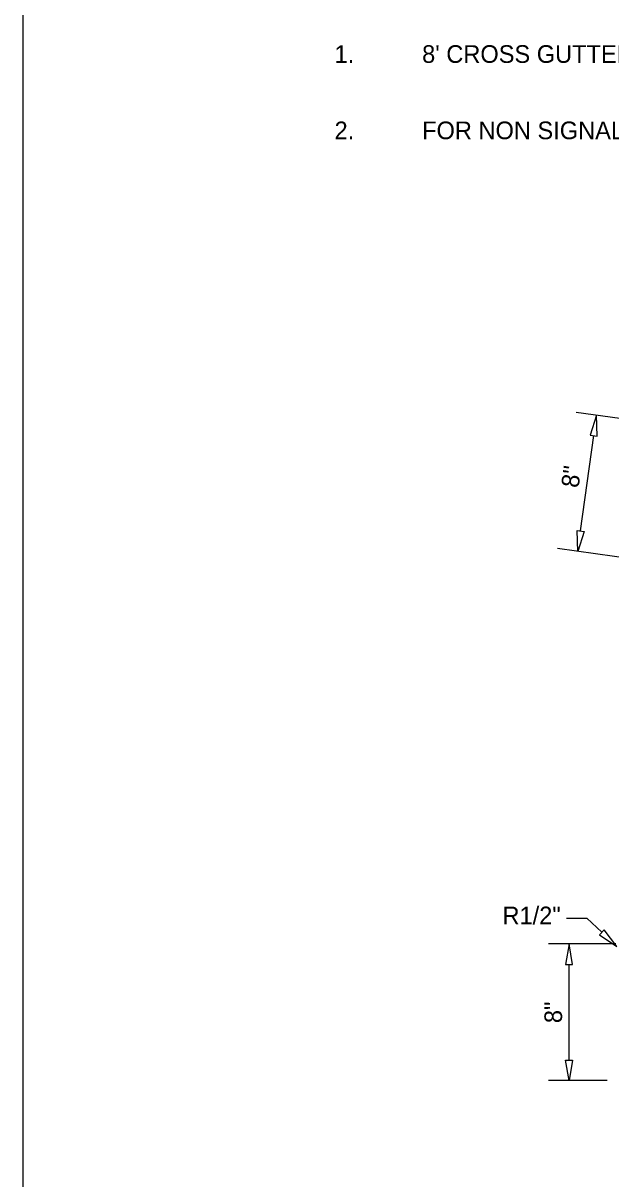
# Model space of a CAD drawing. Extents: x 6712067 to 6713867, y 1867712 to 1869162.
# Drawn here: x 6712066.9 to 6712266.7, y 1868381.6 to 1868774.4 of the extents above; entities that cross this region are included whole.
import ezdxf

# ---------------------------------------------------------------- set-up
doc = ezdxf.new("R2010")
doc.units = 0
for name, color, linetype in [('Control (1)', 7, 'Continuous'), ('Default', 7, 'Continuous'), ('G-MARK', 7, 'Continuous'), ('G-TEXT', 7, 'Continuous'), ('Misc CnstDet(22)', 7, 'Continuous')]:
    doc.layers.add(name, color=color, linetype=linetype)

msp = doc.modelspace()

# ---------------------------------------------------------------- linework, layer by layer
at = {"layer": 'Control (1)'}
msp.add_line((6712252.53, 1868461.51), (6712252.53, 1868461.51), dxfattribs=at)
at = {"layer": 'Default'}
msp.add_lwpolyline([(6712066.89, 1869162.31), (6713866.89, 1869162.31), (6713866.89, 1867712.31), (6712066.89, 1867712.31)], close=True, dxfattribs=at)
at = {"layer": 'G-MARK'}
for p, q in [((6712280.72, 1868638.6), (6712254.9, 1868642.11)), ((6712256.46, 1868601.81), (6712260.89, 1868634.24)), ((6712274.41, 1868592.29), (6712248.59, 1868595.82)), ((6712251.62, 1868470.2), (6712258.59, 1868470.2)), ((6712258.59, 1868470.2), (6712263.69, 1868465.41)), ((6712268.44, 1868461.51), (6712245.53, 1868461.51)), ((6712252.53, 1868421.96), (6712252.53, 1868454.51)), ((6712265.53, 1868414.98), (6712245.53, 1868414.98))]:
    msp.add_line(p, q, dxfattribs=at)
at = {"layer": 'G-TEXT'}
for points in [[(6712259.72, 1868634.4), (6712262.04, 1868634.08), (6712261.83, 1868641.17)], [(6712255.31, 1868601.95), (6712257.63, 1868601.65), (6712255.52, 1868594.88)], [(6712264.49, 1868466.26), (6712262.89, 1868464.56), (6712268.76, 1868460.59)], [(6712251.36, 1868454.51), (6712253.68, 1868454.51), (6712252.53, 1868461.51)], [(6712251.36, 1868421.96), (6712253.68, 1868421.96), (6712252.53, 1868414.98)]]:
    msp.add_lwpolyline(points, close=True, dxfattribs=at)
at = {"layer": 'Misc CnstDet(22)'}
msp.add_line((6712261.83, 1868641.17), (6712261.83, 1868641.17), dxfattribs=at)

# ---------------------------------------------------------------- texts
for s, p in [('1.', (6712172.79, 1868760.94)), ("8' CROSS GUTTER IS USED FOR LOCAL STREETS.", (6712202.56, 1868760.94)), ('2.', (6712172.79, 1868734.99)), ('FOR NON SIGNALIZED INTERSECTIONS (DESIGN IS REQUIRED ON PLAN).', (6712202.56, 1868734.99))]:
    msp.add_text(s, height=6, dxfattribs=at).set_placement(p)
for s, rotation, p in [('8"', 82.2494, (6712255.74, 1868616.26)), ('R1/2"', 0.01, (6712229.89, 1868468.13)), ('8"', 90, (6712250.14, 1868434.53))]:
    msp.add_text(s, height=6, rotation=rotation, dxfattribs=at).set_placement(p)

doc.saveas('drawing.dxf')
